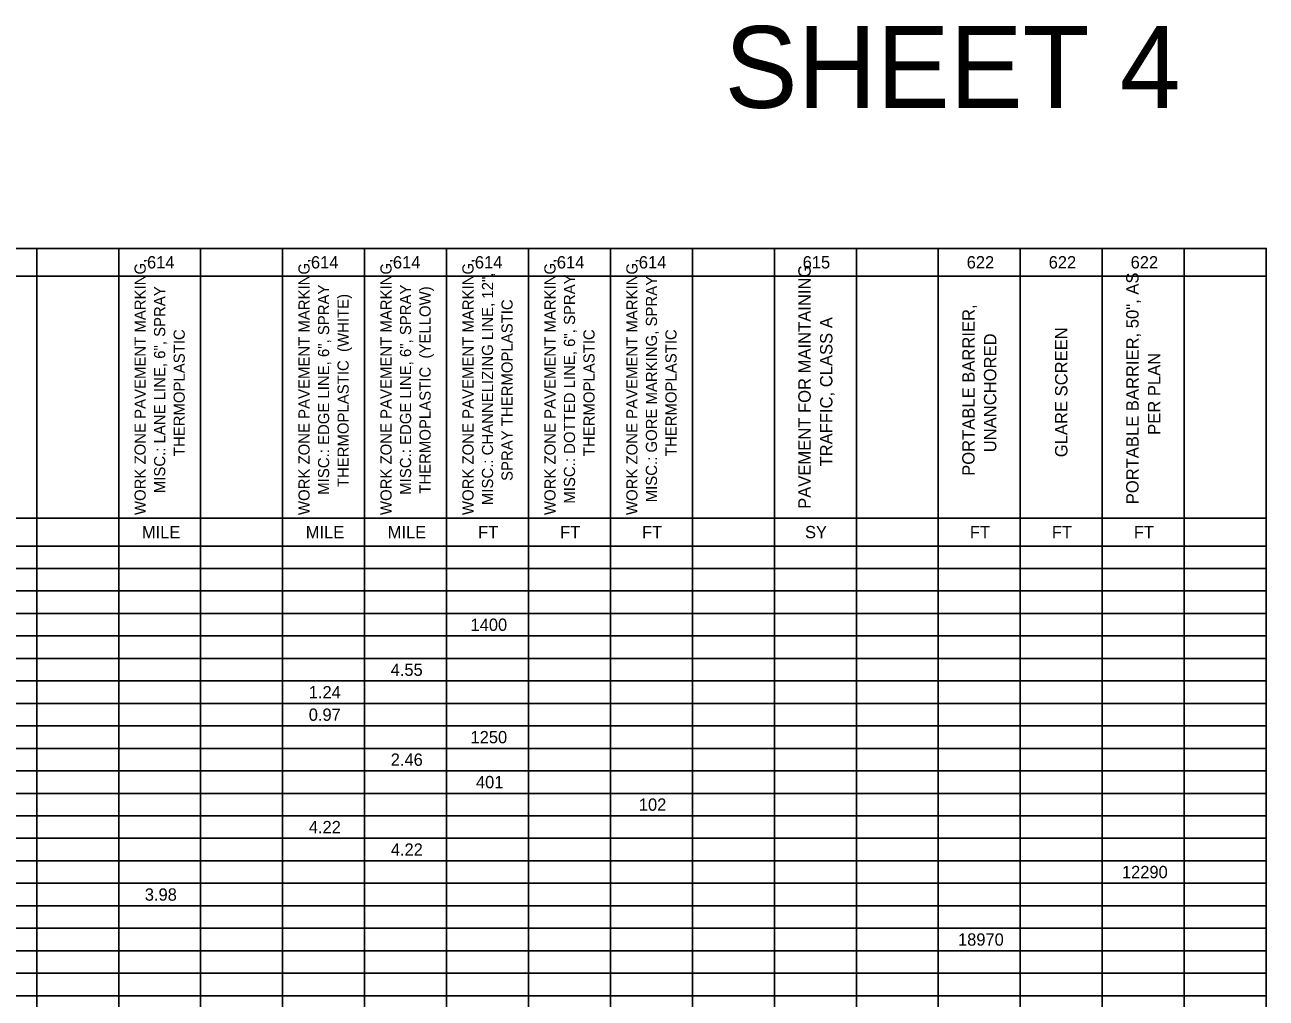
# Model space of a CAD drawing. Extents: x 91011267 to 91022583, y 37007614 to 37014266.
# Drawn here: x 91012044 to 91012802, y 37009486 to 37010081 of the extents above; entities that cross this region are included whole.
import ezdxf

# ---------------------------------------------------------------- set-up
doc = ezdxf.new("R2010")
doc.units = 0
doc.layers.add('SC_Scratch2', color=7, linetype='Continuous')
doc.layers.add('SH_Data', color=7, linetype='Continuous')

msp = doc.modelspace()

# ---------------------------------------------------------------- linework, layer by layer
at = {"layer": 'SC_Scratch2'}
msp.add_lwpolyline([(91011277.35, 37009944.63), (91012802.35, 37009944.63), (91012802.35, 37008894.63), (91011277.35, 37008894.63)], close=True, dxfattribs=at)
at = {"layer": 'SH_Data'}
for p, q in [((91012000.97, 37009944.63), (91012551.92, 37009944.63)), ((91012051.05, 37009944.63), (91012051.05, 37009853.7)), ((91012101.14, 37009944.63), (91012101.14, 37009853.7)), ((91012151.23, 37009944.63), (91012151.23, 37009853.7)), ((91012201.31, 37009944.63), (91012201.31, 37009853.7)), ((91012251.4, 37009944.63), (91012251.4, 37009853.7)), ((91012301.49, 37009944.63), (91012301.49, 37009853.7)), ((91012351.57, 37009944.63), (91012351.57, 37009853.7)), ((91012401.66, 37009944.63), (91012401.66, 37009853.7)), ((91012451.75, 37009944.63), (91012451.75, 37009853.7)), ((91012501.83, 37009944.63), (91012501.83, 37009853.7)), ((91012551.92, 37009944.63), (91012602, 37009944.63)), ((91012551.92, 37009944.63), (91012551.92, 37009853.7)), ((91012602, 37009944.63), (91012652.09, 37009944.63)), ((91012602, 37009944.63), (91012602, 37009853.7)), ((91012652.09, 37009944.63), (91012702.18, 37009944.63)), ((91012652.09, 37009944.63), (91012652.09, 37009853.7)), ((91012702.18, 37009944.63), (91012802.35, 37009944.63)), ((91012702.18, 37009944.63), (91012702.18, 37009853.7)), ((91012752.26, 37009944.63), (91012752.26, 37009853.7)), ((91012802.35, 37009944.63), (91012802.35, 37009853.7)), ((91012000.97, 37009927.62), (91012551.92, 37009927.62)), ((91012551.92, 37009927.62), (91012602, 37009927.62)), ((91012602, 37009927.62), (91012652.09, 37009927.62)), ((91012652.09, 37009927.62), (91012702.18, 37009927.62)), ((91012702.18, 37009927.62), (91012802.35, 37009927.62)), ((91012051.05, 37009853.7), (91012051.05, 37009779.77)), ((91012101.14, 37009853.7), (91012101.14, 37009779.77)), ((91012151.23, 37009853.7), (91012151.23, 37009779.77)), ((91012201.31, 37009853.7), (91012201.31, 37009779.77)), ((91012251.4, 37009853.7), (91012251.4, 37009779.77)), ((91012301.49, 37009853.7), (91012301.49, 37009779.77)), ((91012351.57, 37009853.7), (91012351.57, 37009779.77)), ((91012401.66, 37009853.7), (91012401.66, 37009779.77)), ((91012451.75, 37009853.7), (91012451.75, 37009779.77)), ((91012501.83, 37009853.7), (91012501.83, 37009779.77)), ((91012551.92, 37009853.7), (91012551.92, 37009779.77)), ((91012602, 37009853.7), (91012602, 37009779.77)), ((91012652.09, 37009853.7), (91012652.09, 37009779.77)), ((91012702.18, 37009853.7), (91012702.18, 37009779.77)), ((91012752.26, 37009853.7), (91012752.26, 37009779.77)), ((91012802.35, 37009853.7), (91012802.35, 37009779.77)), ((91012000.97, 37009779.77), (91012551.92, 37009779.77)), ((91012051.05, 37009779.77), (91012051.05, 37009762.76)), ((91012101.14, 37009779.77), (91012101.14, 37009762.76)), ((91012151.23, 37009779.77), (91012151.23, 37009762.76)), ((91012201.31, 37009779.77), (91012201.31, 37009762.76)), ((91012251.4, 37009779.77), (91012251.4, 37009762.76)), ((91012301.49, 37009779.77), (91012301.49, 37009762.76)), ((91012351.57, 37009779.77), (91012351.57, 37009762.76)), ((91012401.66, 37009779.77), (91012401.66, 37009762.76)), ((91012451.75, 37009779.77), (91012451.75, 37009762.76)), ((91012501.83, 37009779.77), (91012501.83, 37009762.76)), ((91012551.92, 37009779.77), (91012602, 37009779.77)), ((91012551.92, 37009779.77), (91012551.92, 37009762.76)), ((91012602, 37009779.77), (91012652.09, 37009779.77)), ((91012602, 37009779.77), (91012602, 37009762.76)), ((91012652.09, 37009779.77), (91012702.18, 37009779.77)), ((91012652.09, 37009779.77), (91012652.09, 37009762.76)), ((91012702.18, 37009779.77), (91012802.35, 37009779.77)), ((91012702.18, 37009779.77), (91012702.18, 37009762.76)), ((91012752.26, 37009779.77), (91012752.26, 37009762.76)), ((91012802.35, 37009779.77), (91012802.35, 37009762.76)), ((91012000.97, 37009762.76), (91012551.92, 37009762.76)), ((91012051.05, 37009762.76), (91012051.05, 37009652.86)), ((91012101.14, 37009762.76), (91012101.14, 37009652.86)), ((91012151.23, 37009762.76), (91012151.23, 37009652.86)), ((91012201.31, 37009762.76), (91012201.31, 37009652.86)), ((91012251.4, 37009762.76), (91012251.4, 37009652.86)), ((91012301.49, 37009762.76), (91012301.49, 37009652.86)), ((91012351.57, 37009762.76), (91012351.57, 37009652.86)), ((91012401.66, 37009762.76), (91012401.66, 37009652.86)), ((91012451.75, 37009762.76), (91012451.75, 37009652.86)), ((91012501.83, 37009762.76), (91012501.83, 37009652.86)), ((91012551.92, 37009762.76), (91012602, 37009762.76)), ((91012551.92, 37009762.76), (91012551.92, 37009652.86)), ((91012602, 37009762.76), (91012652.09, 37009762.76)), ((91012602, 37009762.76), (91012602, 37009652.86)), ((91012652.09, 37009762.76), (91012702.18, 37009762.76)), ((91012652.09, 37009762.76), (91012652.09, 37009652.86)), ((91012702.18, 37009762.76), (91012802.35, 37009762.76)), ((91012702.18, 37009762.76), (91012702.18, 37009652.86)), ((91012752.26, 37009762.76), (91012752.26, 37009652.86)), ((91012802.35, 37009762.76), (91012802.35, 37009652.86)), ((91012000.97, 37009749.02), (91012551.92, 37009749.02)), ((91012551.92, 37009749.02), (91012602, 37009749.02)), ((91012602, 37009749.02), (91012652.09, 37009749.02)), ((91012652.09, 37009749.02), (91012702.18, 37009749.02)), ((91012702.18, 37009749.02), (91012802.35, 37009749.02)), ((91012000.97, 37009735.29), (91012551.92, 37009735.29)), ((91012551.92, 37009735.29), (91012602, 37009735.29)), ((91012602, 37009735.29), (91012652.09, 37009735.29)), ((91012652.09, 37009735.29), (91012702.18, 37009735.29)), ((91012702.18, 37009735.29), (91012802.35, 37009735.29)), ((91012000.97, 37009721.55), (91012551.92, 37009721.55)), ((91012551.92, 37009721.55), (91012602, 37009721.55)), ((91012602, 37009721.55), (91012652.09, 37009721.55)), ((91012652.09, 37009721.55), (91012702.18, 37009721.55)), ((91012702.18, 37009721.55), (91012802.35, 37009721.55)), ((91012000.97, 37009707.81), (91012551.92, 37009707.81)), ((91012551.92, 37009707.81), (91012602, 37009707.81)), ((91012602, 37009707.81), (91012652.09, 37009707.81)), ((91012652.09, 37009707.81), (91012702.18, 37009707.81)), ((91012702.18, 37009707.81), (91012802.35, 37009707.81)), ((91012000.97, 37009694.07), (91012551.92, 37009694.07)), ((91012551.92, 37009694.07), (91012602, 37009694.07)), ((91012602, 37009694.07), (91012652.09, 37009694.07)), ((91012652.09, 37009694.07), (91012702.18, 37009694.07)), ((91012702.18, 37009694.07), (91012802.35, 37009694.07)), ((91012000.97, 37009680.33), (91012551.92, 37009680.33)), ((91012551.92, 37009680.33), (91012602, 37009680.33)), ((91012602, 37009680.33), (91012652.09, 37009680.33)), ((91012652.09, 37009680.33), (91012702.18, 37009680.33)), ((91012702.18, 37009680.33), (91012802.35, 37009680.33)), ((91012000.97, 37009666.59), (91012551.92, 37009666.59)), ((91012551.92, 37009666.59), (91012602, 37009666.59)), ((91012602, 37009666.59), (91012652.09, 37009666.59)), ((91012652.09, 37009666.59), (91012702.18, 37009666.59)), ((91012702.18, 37009666.59), (91012802.35, 37009666.59)), ((91012000.97, 37009652.86), (91012551.92, 37009652.86)), ((91012051.05, 37009652.86), (91012051.05, 37009639.12)), ((91012101.14, 37009652.86), (91012101.14, 37009639.12)), ((91012151.23, 37009652.86), (91012151.23, 37009639.12)), ((91012201.31, 37009652.86), (91012201.31, 37009639.12)), ((91012251.4, 37009652.86), (91012251.4, 37009639.12)), ((91012301.49, 37009652.86), (91012301.49, 37009639.12)), ((91012351.57, 37009652.86), (91012351.57, 37009639.12)), ((91012401.66, 37009652.86), (91012401.66, 37009639.12)), ((91012451.75, 37009652.86), (91012451.75, 37009639.12)), ((91012501.83, 37009652.86), (91012501.83, 37009639.12)), ((91012551.92, 37009652.86), (91012602, 37009652.86)), ((91012551.92, 37009652.86), (91012551.92, 37009639.12)), ((91012602, 37009652.86), (91012652.09, 37009652.86)), ((91012602, 37009652.86), (91012602, 37009639.12)), ((91012652.09, 37009652.86), (91012702.18, 37009652.86)), ((91012652.09, 37009652.86), (91012652.09, 37009639.12)), ((91012702.18, 37009652.86), (91012802.35, 37009652.86)), ((91012702.18, 37009652.86), (91012702.18, 37009639.12)), ((91012752.26, 37009652.86), (91012752.26, 37009639.12)), ((91012802.35, 37009652.86), (91012802.35, 37009639.12)), ((91012000.97, 37009639.12), (91012551.92, 37009639.12)), ((91012051.05, 37009639.12), (91012051.05, 37009611.64)), ((91012101.14, 37009639.12), (91012101.14, 37009611.64)), ((91012151.23, 37009639.12), (91012151.23, 37009611.64)), ((91012201.31, 37009639.12), (91012201.31, 37009611.64)), ((91012251.4, 37009639.12), (91012251.4, 37009611.64)), ((91012301.49, 37009639.12), (91012301.49, 37009611.64)), ((91012351.57, 37009639.12), (91012351.57, 37009611.64)), ((91012401.66, 37009639.12), (91012401.66, 37009611.64)), ((91012451.75, 37009639.12), (91012451.75, 37009611.64)), ((91012501.83, 37009639.12), (91012501.83, 37009611.64)), ((91012551.92, 37009639.12), (91012602, 37009639.12)), ((91012551.92, 37009639.12), (91012551.92, 37009611.64)), ((91012602, 37009639.12), (91012652.09, 37009639.12)), ((91012602, 37009639.12), (91012602, 37009611.64)), ((91012652.09, 37009639.12), (91012702.18, 37009639.12)), ((91012652.09, 37009639.12), (91012652.09, 37009611.64)), ((91012702.18, 37009639.12), (91012802.35, 37009639.12)), ((91012702.18, 37009639.12), (91012702.18, 37009611.64)), ((91012752.26, 37009639.12), (91012752.26, 37009611.64)), ((91012802.35, 37009639.12), (91012802.35, 37009611.64)), ((91012000.97, 37009625.38), (91012551.92, 37009625.38)), ((91012551.92, 37009625.38), (91012602, 37009625.38)), ((91012602, 37009625.38), (91012652.09, 37009625.38)), ((91012652.09, 37009625.38), (91012702.18, 37009625.38)), ((91012702.18, 37009625.38), (91012802.35, 37009625.38)), ((91012000.97, 37009611.64), (91012551.92, 37009611.64)), ((91012051.05, 37009611.64), (91012051.05, 37009597.9)), ((91012101.14, 37009611.64), (91012101.14, 37009597.9)), ((91012151.23, 37009611.64), (91012151.23, 37009597.9)), ((91012201.31, 37009611.64), (91012201.31, 37009597.9)), ((91012251.4, 37009611.64), (91012251.4, 37009597.9)), ((91012301.49, 37009611.64), (91012301.49, 37009597.9)), ((91012351.57, 37009611.64), (91012351.57, 37009597.9)), ((91012401.66, 37009611.64), (91012401.66, 37009597.9)), ((91012451.75, 37009611.64), (91012451.75, 37009597.9)), ((91012501.83, 37009611.64), (91012501.83, 37009597.9)), ((91012551.92, 37009611.64), (91012602, 37009611.64)), ((91012551.92, 37009611.64), (91012551.92, 37009597.9)), ((91012602, 37009611.64), (91012652.09, 37009611.64)), ((91012602, 37009611.64), (91012602, 37009597.9)), ((91012652.09, 37009611.64), (91012702.18, 37009611.64)), ((91012652.09, 37009611.64), (91012652.09, 37009597.9)), ((91012702.18, 37009611.64), (91012802.35, 37009611.64)), ((91012702.18, 37009611.64), (91012702.18, 37009597.9)), ((91012752.26, 37009611.64), (91012752.26, 37009597.9)), ((91012802.35, 37009611.64), (91012802.35, 37009597.9)), ((91012000.97, 37009597.9), (91012551.92, 37009597.9)), ((91012051.05, 37009597.9), (91012051.05, 37009584.17)), ((91012101.14, 37009597.9), (91012101.14, 37009584.17)), ((91012151.23, 37009597.9), (91012151.23, 37009584.17)), ((91012201.31, 37009597.9), (91012201.31, 37009584.17)), ((91012251.4, 37009597.9), (91012251.4, 37009584.17)), ((91012301.49, 37009597.9), (91012301.49, 37009584.17)), ((91012351.57, 37009597.9), (91012351.57, 37009584.17)), ((91012401.66, 37009597.9), (91012401.66, 37009584.17)), ((91012451.75, 37009597.9), (91012451.75, 37009584.17)), ((91012501.83, 37009597.9), (91012501.83, 37009584.17)), ((91012551.92, 37009597.9), (91012602, 37009597.9)), ((91012551.92, 37009597.9), (91012551.92, 37009584.17)), ((91012602, 37009597.9), (91012652.09, 37009597.9)), ((91012602, 37009597.9), (91012602, 37009584.17)), ((91012652.09, 37009597.9), (91012702.18, 37009597.9)), ((91012652.09, 37009597.9), (91012652.09, 37009584.17)), ((91012702.18, 37009597.9), (91012802.35, 37009597.9)), ((91012702.18, 37009597.9), (91012702.18, 37009584.17)), ((91012752.26, 37009597.9), (91012752.26, 37009584.17)), ((91012802.35, 37009597.9), (91012802.35, 37009584.17)), ((91012000.97, 37009584.17), (91012551.92, 37009584.17)), ((91012051.05, 37009584.17), (91012051.05, 37009570.43)), ((91012101.14, 37009584.17), (91012101.14, 37009570.43)), ((91012151.23, 37009584.17), (91012151.23, 37009570.43)), ((91012201.31, 37009584.17), (91012201.31, 37009570.43)), ((91012251.4, 37009584.17), (91012251.4, 37009570.43)), ((91012301.49, 37009584.17), (91012301.49, 37009570.43)), ((91012351.57, 37009584.17), (91012351.57, 37009570.43)), ((91012401.66, 37009584.17), (91012401.66, 37009570.43)), ((91012451.75, 37009584.17), (91012451.75, 37009570.43)), ((91012501.83, 37009584.17), (91012501.83, 37009570.43)), ((91012551.92, 37009584.17), (91012602, 37009584.17)), ((91012551.92, 37009584.17), (91012551.92, 37009570.43)), ((91012602, 37009584.17), (91012652.09, 37009584.17)), ((91012602, 37009584.17), (91012602, 37009570.43)), ((91012652.09, 37009584.17), (91012702.18, 37009584.17)), ((91012652.09, 37009584.17), (91012652.09, 37009570.43)), ((91012702.18, 37009584.17), (91012802.35, 37009584.17)), ((91012702.18, 37009584.17), (91012702.18, 37009570.43)), ((91012752.26, 37009584.17), (91012752.26, 37009570.43)), ((91012802.35, 37009584.17), (91012802.35, 37009570.43)), ((91012000.97, 37009570.43), (91012551.92, 37009570.43)), ((91012051.05, 37009570.43), (91012051.05, 37009364.35)), ((91012101.14, 37009570.43), (91012101.14, 37009364.35)), ((91012151.23, 37009570.43), (91012151.23, 37009364.35)), ((91012201.31, 37009570.43), (91012201.31, 37009364.35)), ((91012251.4, 37009570.43), (91012251.4, 37009364.35)), ((91012301.49, 37009570.43), (91012301.49, 37009364.35)), ((91012351.57, 37009570.43), (91012351.57, 37009364.35)), ((91012401.66, 37009570.43), (91012401.66, 37009364.35)), ((91012451.75, 37009570.43), (91012451.75, 37009364.35)), ((91012501.83, 37009570.43), (91012501.83, 37009364.35)), ((91012551.92, 37009570.43), (91012602, 37009570.43)), ((91012551.92, 37009570.43), (91012551.92, 37009364.35)), ((91012602, 37009570.43), (91012652.09, 37009570.43)), ((91012602, 37009570.43), (91012602, 37009364.35)), ((91012652.09, 37009570.43), (91012702.18, 37009570.43)), ((91012652.09, 37009570.43), (91012652.09, 37009364.35)), ((91012702.18, 37009570.43), (91012802.35, 37009570.43)), ((91012702.18, 37009570.43), (91012702.18, 37009364.35)), ((91012752.26, 37009570.43), (91012752.26, 37009364.35)), ((91012802.35, 37009570.43), (91012802.35, 37009364.35)), ((91012000.97, 37009556.69), (91012551.92, 37009556.69)), ((91012551.92, 37009556.69), (91012602, 37009556.69)), ((91012602, 37009556.69), (91012652.09, 37009556.69)), ((91012652.09, 37009556.69), (91012702.18, 37009556.69)), ((91012702.18, 37009556.69), (91012802.35, 37009556.69)), ((91012000.97, 37009542.95), (91012551.92, 37009542.95)), ((91012551.92, 37009542.95), (91012602, 37009542.95)), ((91012602, 37009542.95), (91012652.09, 37009542.95)), ((91012652.09, 37009542.95), (91012702.18, 37009542.95)), ((91012702.18, 37009542.95), (91012802.35, 37009542.95)), ((91012000.97, 37009529.21), (91012551.92, 37009529.21)), ((91012551.92, 37009529.21), (91012602, 37009529.21)), ((91012602, 37009529.21), (91012652.09, 37009529.21)), ((91012652.09, 37009529.21), (91012702.18, 37009529.21)), ((91012702.18, 37009529.21), (91012802.35, 37009529.21)), ((91012000.97, 37009515.47), (91012551.92, 37009515.47)), ((91012551.92, 37009515.47), (91012602, 37009515.47)), ((91012602, 37009515.47), (91012652.09, 37009515.47)), ((91012652.09, 37009515.47), (91012702.18, 37009515.47)), ((91012702.18, 37009515.47), (91012802.35, 37009515.47)), ((91012000.97, 37009501.74), (91012551.92, 37009501.74)), ((91012551.92, 37009501.74), (91012602, 37009501.74)), ((91012602, 37009501.74), (91012652.09, 37009501.74)), ((91012652.09, 37009501.74), (91012702.18, 37009501.74)), ((91012702.18, 37009501.74), (91012802.35, 37009501.74)), ((91012000.97, 37009488), (91012551.92, 37009488)), ((91012551.92, 37009488), (91012602, 37009488)), ((91012602, 37009488), (91012652.09, 37009488)), ((91012652.09, 37009488), (91012702.18, 37009488)), ((91012702.18, 37009488), (91012802.35, 37009488))]:
    msp.add_line(p, q, dxfattribs=at)

# ---------------------------------------------------------------- texts
at = {"layer": 'SC_Scratch2'}
msp.add_text('SHEET 4', height=50, rotation=360, dxfattribs=at).set_placement((91012471.4, 37010030.48))
at = {"layer": 'SH_Data'}
for s, p in [('614', (91012118.47, 37009932.37)), ('614', (91012218.64, 37009932.37)), ('614', (91012268.73, 37009932.37)), ('614', (91012318.81, 37009932.37)), ('614', (91012368.9, 37009932.37)), ('614', (91012418.99, 37009932.37)), ('615', (91012519.12, 37009932.37)), ('622', (91012619.35, 37009932.37)), ('622', (91012669.44, 37009932.37)), ('622', (91012719.53, 37009932.37)), ('MILE', (91012115.32, 37009767.51)), ('MILE', (91012215.49, 37009767.51)), ('MILE', (91012265.58, 37009767.51)), ('FT', (91012320.8, 37009767.51)), ('FT', (91012370.89, 37009767.51)), ('FT', (91012420.98, 37009767.51)), ('SY', (91012520.55, 37009767.51)), ('FT', (91012621.32, 37009767.51)), ('FT', (91012671.41, 37009767.51)), ('FT', (91012721.49, 37009767.51)), ('1400', (91012316.16, 37009710.92)), ('4.55', (91012267.36, 37009683.44)), ('1.24', (91012217.32, 37009669.7)), ('0.97', (91012217.3, 37009655.96)), ('1250', (91012316.16, 37009642.23)), ('2.46', (91012267.39, 37009628.49)), ('401', (91012319.46, 37009614.75)), ('102', (91012419.01, 37009601.01)), ('4.22', (91012217.34, 37009587.27)), ('4.22', (91012267.43, 37009573.53)), ('12290', (91012714.21, 37009559.8)), ('3.98', (91012117.12, 37009546.06)), ('18970', (91012614.03, 37009518.58))]:
    msp.add_text(s, height=7.523, dxfattribs=at).set_placement(p)
for s, height, p in [('WORK ZONE PAVEMENT MARKING, ', 6.821, (91012117.66, 37009781.69)), ('WORK ZONE PAVEMENT MARKING, ', 6.821, (91012217.83, 37009781.69)), ('WORK ZONE PAVEMENT MARKING, ', 6.821, (91012267.92, 37009781.69)), ('WORK ZONE PAVEMENT MARKING, ', 6.821, (91012318, 37009781.69)), ('WORK ZONE PAVEMENT MARKING, ', 6.821, (91012368.09, 37009781.69)), ('WORK ZONE PAVEMENT MARKING, ', 6.821, (91012418.18, 37009781.69)), ('PAVEMENT FOR MAINTAINING ', 7.5789, (91012524.03, 37009785.48)), ('MISC.: CHANNELIZING LINE, 12", ', 6.821, (91012329.94, 37009787.75)), ('MISC.: DOTTED LINE, 6", SPRAY ', 6.821, (91012380.03, 37009788.66)), ('MISC.: GORE MARKING, SPRAY ', 6.821, (91012430.11, 37009789.47)), ('PORTABLE BARRIER, 50", AS ', 7.5789, (91012724.38, 37009788.29)), ('MISC.: LANE LINE, 6", SPRAY ', 6.821, (91012129.59, 37009795.05)), ('MISC.: EDGE LINE, 6", SPRAY ', 6.821, (91012229.77, 37009794.1)), ('THERMOPLASTIC  (WHITE)', 6.821, (91012241.7, 37009798.74)), ('MISC.: EDGE LINE, 6", SPRAY ', 6.821, (91012279.85, 37009794.1)), ('THERMOPLASTIC  (YELLOW)', 6.821, (91012291.79, 37009794.72)), ('SPRAY THERMOPLASTIC', 6.821, (91012341.88, 37009802.52)), ('PORTABLE BARRIER, ', 7.5789, (91012624.21, 37009805.66)), ('TRAFFIC, CLASS A', 7.5789, (91012537.3, 37009811.37)), ('THERMOPLASTIC', 6.821, (91012141.53, 37009817.67)), ('THERMOPLASTIC', 6.821, (91012391.96, 37009817.67)), ('THERMOPLASTIC', 6.821, (91012442.05, 37009817.67)), ('GLARE SCREEN', 7.5789, (91012680.92, 37009817.02)), ('UNANCHORED', 7.579, (91012637.47, 37009820.04)), ('PER PLAN', 7.579, (91012737.64, 37009830.69))]:
    msp.add_text(s, height=height, rotation=90, dxfattribs=at).set_placement(p)

doc.saveas('drawing.dxf')
